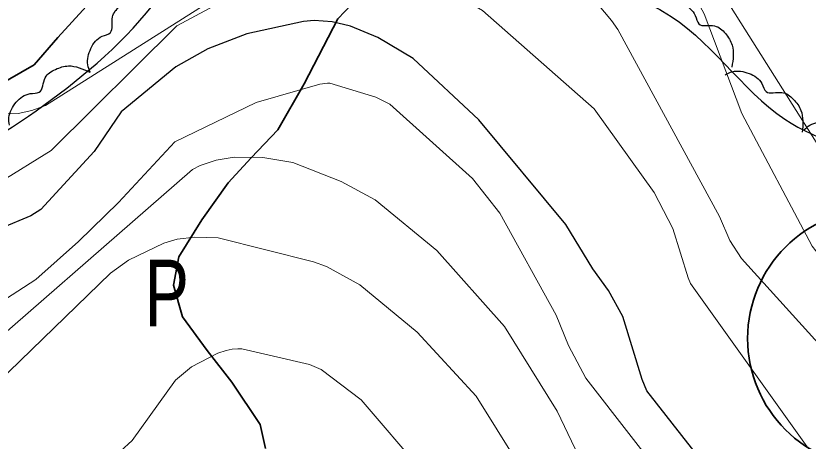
# Model space of a CAD drawing. Extents: x 483847 to 488453, y 4383581 to 4386795.
# Drawn here: x 485100.7 to 485279.2, y 4385920.7 to 4386016.5 of the extents above; entities that cross this region are included whole.
import ezdxf
from ezdxf.enums import TextEntityAlignment as Align

# ---------------------------------------------------------------- set-up
doc = ezdxf.new("R2010")
doc.units = 0
doc.header["$LTSCALE"] = 3.8
doc.linetypes.add('LONG_DASHED', pattern=[7.5, 6, -1.5])
for name, color, linetype, lineweight in [('27', 7, 'Continuous', 25), ('6', 7, 'Continuous', 35), ('8', 7, 'Continuous', 25), ('9', 7, 'Continuous', 13)]:
    doc.layers.add(name, color=color, linetype=linetype, lineweight=lineweight)
doc.layers.add('31', color=7, linetype='Continuous')

msp = doc.modelspace()

# ---------------------------------------------------------------- linework, layer by layer
at = {"layer": '27'}
for points in [[(484896.77, 4385939.39), (484928.08, 4385945.7), (484941.54, 4385949.9), (484943.64, 4385951.17), (484944.49, 4385954.95), (484944.91, 4385960.42), (484949.53, 4385968.84), (484955.42, 4385972.2), (484962.57, 4385974.73), (484968.88, 4385974.73), (484977.29, 4385970.52), (484996.21, 4385954.95), (485010.93, 4385939.81), (485018.5, 4385936.44), (485032.8, 4385935.6), (485057.19, 4385936.44), (485058.87, 4385938.96), (485055.51, 4385941.07), (485047.1, 4385941.49), (485027.75, 4385946.54), (485023.55, 4385952.01), (485021.02, 4385958.32), (485020.6, 4385968.42), (485023.55, 4385978.51), (485029.44, 4385983.56), (485068.97, 4386000.81), (485104.29, 4386026.06), (485129.94, 4386056.35), (485148.45, 4386080.76), (485167.37, 4386097.16), (485173.68, 4386114.41), (485169.48, 4386130.4), (485162.33, 4386148.07), (485165.69, 4386159.85), (485168.63, 4386167.01), (485172.42, 4386169.95), (485174.1, 4386172.06), (485175.78, 4386172.48), (485193.87, 4386159.85), (485214.89, 4386145.13), (485219.1, 4386136.71), (485218.68, 4386131.66), (485211.53, 4386131.24), (485205.22, 4386135.45), (485199.75, 4386136.71), (485196.81, 4386135.45), (485191.34, 4386108.52), (485178.31, 4386082.02), (485171.58, 4386074.86), (485174.94, 4386074.02), (485176.2, 4386076.13), (485191.34, 4386093.38)], [(484770.09, 4385821.2), (484778.9, 4385832.4), (484794.27, 4385845.21), (484801.95, 4385855.46), (484801.31, 4385859.95), (484800.03, 4385867), (484801.31, 4385872.12), (484804.51, 4385875.97), (484808.35, 4385877.89), (484852.54, 4385906.08), (484922.98, 4385925.3), (484958.84, 4385927.22), (484993.43, 4385913.13), (485031.21, 4385911.84), (485074.11, 4385922.09), (485086.28, 4385934.27), (485090.76, 4385947.72), (485086.92, 4385956.05), (485084.36, 4385957.97), (485051.06, 4385961.82), (485052.34, 4385965.02), (485054.26, 4385966.3), (485113.82, 4386001.54), (485138.15, 4386028.45), (485149.04, 4386043.82), (485161.85, 4386049.59), (485183.62, 4386060.48), (485187.46, 4386060.48), (485190.66, 4386058.56), (485190.02, 4386048.95), (485192.59, 4386043.82), (485198.35, 4386037.42), (485204.75, 4386030.37), (485226.53, 4386025.24), (485236.13, 4386022.04), (485246.38, 4386017.56), (485273.91, 4385993.21), (485300.17, 4385981.68), (485306.57, 4385976.55), (485307.21, 4385971.43), (485323.87, 4385923.38), (485329.63, 4385908), (485325.79, 4385894.55), (485332.83, 4385858.67), (485336.67, 4385846.49), (485339.87, 4385840.09), (485344.36, 4385837.53), (485353.96, 4385838.81), (485363.57, 4385845.21), (485376.38, 4385849.7), (485388.54, 4385853.54), (485402.63, 4385867), (485419.28, 4385873.4), (485430.17, 4385870.2), (485440.83, 4385855.64)], [(485117.45, 4386003.77), (485116.89, 4386005.45), (485117.58, 4386009.18), (485120.09, 4386011.89), (485121.96, 4386012.72), (485122.43, 4386016.25), (485124.16, 4386018.68), (485126.77, 4386020.19), (485131.73, 4386020.11)], [(485245.62, 4386019.18), (485247.3, 4386019.74), (485251.04, 4386019.07), (485253.75, 4386016.57), (485254.58, 4386014.69), (485258.11, 4386014.24), (485260.55, 4386012.52), (485262.07, 4386009.9), (485262, 4386004.94)], [(485099.21, 4385991.84), (485099.11, 4385993.61), (485100.75, 4385997.03), (485103.89, 4385998.98), (485105.92, 4385999.28), (485107.29, 4386002.56), (485109.6, 4386004.45), (485112.53, 4386005.22), (485117.29, 4386003.83)], [(485260.46, 4386003.23), (485262.1, 4386003.92), (485265.87, 4386003.52), (485268.76, 4386001.23), (485269.73, 4385999.42), (485273.29, 4385999.24), (485275.85, 4385997.7), (485277.56, 4385995.21), (485277.86, 4385990.26)], [(485278.2, 4385990.75), (485279.59, 4385991.85), (485283.33, 4385992.48), (485286.73, 4385991.05), (485288.15, 4385989.57), (485291.63, 4385990.34), (485294.5, 4385989.55), (485296.82, 4385987.61), (485298.44, 4385982.92)]]:
    msp.add_spline(points, degree=3, dxfattribs=at)
at = {"layer": '6'}
msp.add_lwpolyline([(485096.24, 4386000.56), (485104.76, 4386005.49), (485110.15, 4386011.63), (485124.59, 4386027.56), (485137.59, 4386048.93)], dxfattribs=at)
at = {"layer": '6', "linetype": 'LONG_DASHED'}
msp.add_lwpolyline([(485184.77, 4386028.13), (485173.22, 4386015.8), (485165.66, 4386001.18), (485159.68, 4385990.84), (485153.71, 4385984.47), (485148.53, 4385978.9), (485142.56, 4385970.54), (485137.38, 4385962.19), (485136.19, 4385955.82), (485138.18, 4385948.66), (485143.75, 4385941.1), (485149.33, 4385933.93), (485155.7, 4385924.38), (485156.89, 4385919)], dxfattribs=at)
at = {"layer": '6'}
msp.add_circle((485294.65, 4385943.81), 29.1, dxfattribs=at)
at = {"layer": '8'}
msp.add_lwpolyline([(485301.86, 4385856.65), (485242.86, 4385932.02), (485241.76, 4385934.52), (485237.45, 4385948.72), (485234.23, 4385954.63), (485230.68, 4385959.49), (485224.56, 4385969.47), (485205.02, 4385993.05), (485190.19, 4386006.87), (485182.24, 4386011.66), (485176.08, 4386014.2), (485171.92, 4386015.19), (485167.91, 4386015.43), (485165.5, 4386015.2), (485152.74, 4386012.45), (485143.94, 4386009.04), (485136.72, 4386005.04), (485124.36, 4385994.87), (485118.28, 4385985.9), (485106.26, 4385972.84), (485104.01, 4385971.45), (485097.23, 4385968.56)], dxfattribs=at)
at = {"layer": '9'}
for points in [[(485447.3, 4385726.14), (485428.73, 4385784.65), (485427.18, 4385786.41), (485419.62, 4385798.52), (485411.36, 4385808.57), (485410.62, 4385809.15), (485382.59, 4385836.88), (485368.77, 4385848.5), (485368, 4385849.34), (485366.09, 4385851.94), (485359.62, 4385871.02), (485318.01, 4385932.92), (485315.08, 4385935.7), (485285.03, 4385958.28), (485280.11, 4385964.58), (485264.26, 4385994.47), (485255.78, 4386016.98), (485254.3, 4386019.62), (485223.05, 4386054.79), (485212.59, 4386062.48), (485211.91, 4386062.77), (485210.06, 4386063.33), (485206.98, 4386063.82), (485206.06, 4386063.8)], [(485312.33, 4385908.6), (485264.17, 4385961.85), (485261.55, 4385965.88), (485259.21, 4385971.25), (485236.27, 4386013.44), (485234.9, 4386015.47), (485227.77, 4386024.04), (485205.5, 4386041.75), (485202.52, 4386043.19), (485195.73, 4386045.3), (485188.96, 4386045.48), (485188.09, 4386045.33), (485183.2, 4386043.77), (485161.69, 4386030.8), (485107.33, 4385996.33), (485104.3, 4385995.17), (485101.2, 4385994.5), (485097.98, 4385994.42)], [(485283.14, 4385984.55), (485249.36, 4386038.25)], [(485096.87, 4385978.98), (485108.65, 4385986.18), (485136.96, 4386014.28), (485147.42, 4386019.86), (485158.52, 4386023.48), (485171.32, 4386025.27), (485182.07, 4386024.95), (485194.02, 4386023.02), (485196.51, 4386022.36), (485204.39, 4386018.57), (485205.82, 4386017.69), (485230.99, 4385995.56), (485244.53, 4385976.66), (485248.72, 4385968.59), (485252.12, 4385957.49), (485252.7, 4385956.17), (485312.99, 4385871.71)], [(485278.04, 4385871.84), (485229.13, 4385934.88), (485225.19, 4385942.2), (485222.38, 4385949.01), (485209.72, 4385972.02), (485203.54, 4385979.87), (485184.96, 4385996.62), (485181.74, 4385998.19), (485171.4, 4386001.35), (485170.92, 4386001.34), (485169.13, 4386001.09), (485154.81, 4385996.94), (485136.45, 4385988.09), (485123.77, 4385974.43), (485114.78, 4385965.68), (485105.17, 4385957.12), (485096.98, 4385951.83)], [(485083.35, 4385932.13), (485140.44, 4385981.85), (485142.21, 4385982.81), (485145.81, 4385983.98), (485149.82, 4385984.64), (485156.29, 4385984.58), (485163.11, 4385983.43), (485173.99, 4385979.17), (485181.66, 4385975.05), (485195.55, 4385963.65), (485210.77, 4385946.47), (485222.6, 4385927.39), (485233.96, 4385903.7)], [(485213.84, 4385915.64), (485204.37, 4385930.79), (485191.09, 4385945.24), (485178.15, 4385955.88), (485170.67, 4385959.99), (485167.72, 4385961.04), (485146.22, 4385966.46), (485141.01, 4385966.64), (485136.99, 4385966.14), (485134.02, 4385965.3), (485126.08, 4385961.45), (485122.02, 4385958.5), (485096.49, 4385933.81), (485084.18, 4385924.06), (485071.46, 4385917.05)], [(485192.34, 4385913.74), (485178.49, 4385929.98), (485169.48, 4385936.83), (485166.85, 4385937.96), (485151.59, 4385941.45), (485150.71, 4385941.47), (485149.37, 4385941.38), (485148.04, 4385941.12), (485146.17, 4385940.46), (485140.27, 4385937.39), (485136.64, 4385934.36), (485126.88, 4385920.78), (485124.28, 4385918.38)]]:
    msp.add_lwpolyline(points, dxfattribs=at)

# ---------------------------------------------------------------- texts
at = {"layer": '31', "width": 0.75}
msp.add_text('P', height=15, dxfattribs=at).set_placement((485134.67, 4385946.54), align=Align.CENTER)

doc.saveas('drawing.dxf')
